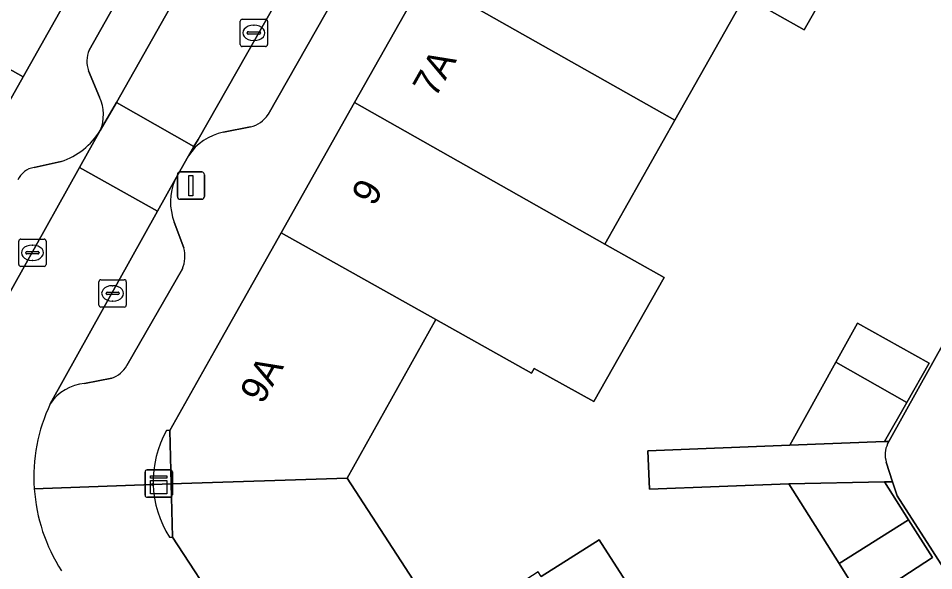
# Model space of a CAD drawing. Extents: x 161798 to 162385, y 382315 to 382833.
# Drawn here: x 162005.25 to 162038.73, y 382639.59 to 382659.78 of the extents above; entities that cross this region are included whole.
import ezdxf

# ---------------------------------------------------------------- set-up
doc = ezdxf.new("R2010")
doc.units = 0
for name, color, linetype in [('IMGEO_Erf', 7, 'Continuous'), ('IMGEO_Kast', 7, 'Continuous'), ('IMGEO_Kolk', 7, 'Continuous'), ('IMGEO_Lichtmast', 7, 'Continuous'), ('IMGEO_Pand', 7, 'Continuous'), ('IMGEO_Pand_nummerreeks', 7, 'Continuous'), ('IMGEO_Pand_overbouw', 7, 'Continuous'), ('IMGEO_Parkeervlak_open', 7, 'Continuous'), ('IMGEO_Rijbaan_lokaal_open', 7, 'Continuous'), ('IMGEO_Voetpad_open', 7, 'Continuous')]:
    doc.layers.add(name, color=color, linetype=linetype)

msp = doc.modelspace()

# ---------------------------------------------------------------- linework, layer by layer
at = {"layer": 'IMGEO_Erf'}
for points in [[(162049.126, 382624.056), (162037.386, 382642.326), (162037.221, 382642.838), (162036.93, 382642.832), (162037.804, 382641.448), (162038.678, 382640.064), (162036.156, 382638.417), (162035.263, 382639.842), (162033.431, 382642.763), (162028.329, 382642.567), (162028.275, 382643.971), (162033.468, 382644.171), (162035.151, 382647.209), (162035.941, 382648.633), (162038.557, 382647.172), (162037.743, 382645.738), (162036.929, 382644.304), (162037.089, 382644.31), (162054.299, 382675.209)], [(162036.559, 382663.871), (162033.985, 382659.354), (162031.821, 382660.586), (162029.259, 382656.056), (162026.698, 382651.527), (162028.865, 382650.298), (162026.302, 382645.768), (162024.119, 382646.981), (162024.02, 382646.802), (162020.518, 382648.763), (162017.274, 382642.968), (162020.91, 382637.369)], [(162024.369, 382639.367), (162026.492, 382640.715), (162029.297, 382636.356)]]:
    msp.add_lwpolyline(points, dxfattribs=at)
at = {"layer": 'IMGEO_Kast'}
for p, q in [((162009.961, 382643.268), (162010.802, 382643.268)), ((162010.802, 382643.268), (162009.961, 382643.268)), ((162009.886, 382642.343), (162009.886, 382643.184)), ((162009.886, 382643.184), (162009.886, 382642.343)), ((162010.886, 382643.193), (162010.886, 382642.352)), ((162010.886, 382642.352), (162010.886, 382643.193)), ((162010.811, 382642.268), (162009.97, 382642.268)), ((162009.97, 382642.268), (162010.811, 382642.268))]:
    msp.add_line(p, q, dxfattribs=at)
for points in [[(162010.081, 382643.058), (162010.681, 382643.058), (162010.681, 382642.973), (162010.081, 382642.973), (162010.081, 382643.058)], [(162010.081, 382642.883), (162010.681, 382642.883), (162010.681, 382642.394), (162010.081, 382642.394), (162010.081, 382642.883)]]:
    msp.add_lwpolyline(points, dxfattribs=at)
msp.add_circle((162010.165, 382642.732), 0.0377, dxfattribs=at)
for centre, start, end in [((162009.964, 382643.19), 92.4484, 184.2845), ((162009.964, 382643.19), 92.4484, 184.2845), ((162010.808, 382643.19), 2.4484, 94.2845), ((162010.808, 382643.19), 2.4484, 94.2845), ((162009.964, 382642.346), 182.4484, 274.2845), ((162009.964, 382642.346), 182.4484, 274.2845), ((162010.808, 382642.346), 272.4484, 4.2845), ((162010.808, 382642.346), 272.4484, 4.2845)]:
    msp.add_arc(centre, 0.0779, start, end, dxfattribs=at)
at = {"layer": 'IMGEO_Kolk'}
for p, q in [((162013.363, 382658.819), (162013.363, 382659.671)), ((162013.438, 382659.745), (162014.29, 382659.745)), ((162014.364, 382659.671), (162014.364, 382658.819)), ((162013.665, 382659.288), (162014.063, 382659.288)), ((162013.851, 382659.525), (162013.876, 382659.525)), ((162013.622, 382659.239), (162013.622, 382659.251)), ((162014.06, 382659.202), (162013.662, 382659.202)), ((162013.874, 382658.965), (162013.849, 382658.965)), ((162014.106, 382659.251), (162014.106, 382659.239)), ((162014.29, 382658.745), (162013.438, 382658.745)), ((162005.267, 382650.781), (162005.267, 382651.633)), ((162005.342, 382651.707), (162006.194, 382651.707)), ((162006.268, 382651.633), (162006.268, 382650.781)), ((162005.569, 382651.25), (162005.967, 382651.25)), ((162005.755, 382651.487), (162005.78, 382651.487)), ((162005.526, 382651.201), (162005.526, 382651.213)), ((162005.964, 382651.164), (162005.566, 382651.164)), ((162005.778, 382650.927), (162005.753, 382650.927)), ((162006.01, 382651.213), (162006.01, 382651.201)), ((162006.194, 382650.707), (162005.342, 382650.707)), ((162008.199, 382649.297), (162008.199, 382650.149)), ((162008.274, 382650.223), (162009.126, 382650.223)), ((162008.687, 382650.003), (162008.712, 382650.003)), ((162009.2, 382650.149), (162009.2, 382649.297)), ((162008.458, 382649.717), (162008.458, 382649.729)), ((162008.896, 382649.68), (162008.498, 382649.68)), ((162008.501, 382649.766), (162008.899, 382649.766)), ((162008.942, 382649.729), (162008.942, 382649.717)), ((162008.71, 382649.443), (162008.685, 382649.443)), ((162009.126, 382649.223), (162008.274, 382649.223))]:
    msp.add_line(p, q, dxfattribs=at)
for points in [[(162013.363, 382658.819), (162013.363, 382659.671)], [(162013.438, 382659.745), (162014.29, 382659.745)], [(162014.364, 382659.671), (162014.364, 382658.819)], [(162014.29, 382658.745), (162013.438, 382658.745)], [(162005.267, 382650.781), (162005.267, 382651.633)], [(162005.342, 382651.707), (162006.194, 382651.707)], [(162006.268, 382651.633), (162006.268, 382650.781)], [(162006.194, 382650.707), (162005.342, 382650.707)], [(162008.199, 382649.297), (162008.199, 382650.149)], [(162008.274, 382650.223), (162009.126, 382650.223)], [(162009.2, 382650.149), (162009.2, 382649.297)], [(162009.126, 382649.223), (162008.274, 382649.223)]]:
    msp.add_lwpolyline(points, dxfattribs=at)
for centre, radius, start, end in [((162013.44, 382659.669), 0.0765, 91.552, 178.448), ((162013.44, 382659.669), 0.0765, 91.552, 178.448), ((162014.288, 382659.669), 0.0765, 1.552, 88.448), ((162014.288, 382659.669), 0.0765, 1.552, 88.448), ((162013.662, 382659.248), 0.0403, 85.8775, 175.7526), ((162014.067, 382659.25), 0.0386, 1.7309, 96.639), ((162013.659, 382659.238), 0.0366, 178.938, 274.7102), ((162014.063, 382659.245), 0.043, 264.8664, 352.4533), ((162013.44, 382658.821), 0.0765, 181.552, 268.448), ((162013.44, 382658.821), 0.0765, 181.552, 268.448), ((162014.288, 382658.821), 0.0765, 271.552, 358.448), ((162014.288, 382658.821), 0.0765, 271.552, 358.448), ((162005.344, 382651.631), 0.0765, 91.552, 178.448), ((162005.344, 382651.631), 0.0765, 91.552, 178.448), ((162006.192, 382651.631), 0.0765, 1.552, 88.448), ((162006.192, 382651.631), 0.0765, 1.552, 88.448), ((162005.566, 382651.21), 0.0403, 85.8775, 175.7526), ((162005.971, 382651.212), 0.0386, 1.7309, 96.639), ((162005.563, 382651.2), 0.0366, 178.938, 274.7102), ((162005.967, 382651.207), 0.043, 264.8664, 352.4533), ((162005.344, 382650.783), 0.0765, 181.552, 268.448), ((162005.344, 382650.783), 0.0765, 181.552, 268.448), ((162006.192, 382650.783), 0.0765, 271.552, 358.448), ((162006.192, 382650.783), 0.0765, 271.552, 358.448), ((162008.276, 382650.147), 0.0765, 91.552, 178.448), ((162008.276, 382650.147), 0.0765, 91.552, 178.448), ((162009.124, 382650.147), 0.0765, 1.552, 88.448), ((162009.124, 382650.147), 0.0765, 1.552, 88.448), ((162008.498, 382649.726), 0.0403, 85.8775, 175.7526), ((162008.495, 382649.716), 0.0366, 178.938, 274.7102), ((162008.899, 382649.723), 0.043, 264.8664, 352.4533), ((162008.903, 382649.728), 0.0386, 1.7309, 96.639), ((162008.276, 382649.299), 0.0765, 181.552, 268.448), ((162008.276, 382649.299), 0.0765, 181.552, 268.448), ((162009.124, 382649.299), 0.0765, 271.552, 358.448), ((162009.124, 382649.299), 0.0765, 271.552, 358.448)]:
    msp.add_arc(centre, radius, start, end, dxfattribs=at)
for centre, major_axis, ratio, start_param, end_param in [((162013.85, 382659.245), (-0.387, 0.002), 0.722429, 4.712389, 7.853982), ((162013.875, 382659.245), (-0.39, 0.002), 0.717154, 1.570796, 4.712389), ((162005.754, 382651.207), (-0.387, 0.002), 0.722429, 4.712389, 7.853982), ((162005.779, 382651.207), (-0.39, 0.002), 0.717154, 1.570796, 4.712389), ((162008.686, 382649.723), (-0.387, 0.002), 0.722429, 4.712389, 7.853982), ((162008.711, 382649.723), (-0.39, 0.002), 0.717154, 1.570796, 4.712389)]:
    msp.add_ellipse(centre, major_axis=major_axis, ratio=ratio, start_param=start_param, end_param=end_param, dxfattribs=at)
at = {"layer": 'IMGEO_Lichtmast'}
for p, q in [((162011.067, 382653.262), (162011.067, 382654.062)), ((162011.067, 382654.062), (162011.067, 382653.262)), ((162011.167, 382654.162), (162011.957, 382654.162)), ((162011.957, 382654.162), (162011.167, 382654.162)), ((162012.057, 382654.062), (162012.057, 382653.262)), ((162012.057, 382653.262), (162012.057, 382654.062)), ((162011.957, 382653.162), (162011.167, 382653.162)), ((162011.167, 382653.162), (162011.957, 382653.162))]:
    msp.add_line(p, q, dxfattribs=at)
msp.add_lwpolyline([(162011.487, 382654.037), (162011.637, 382654.037), (162011.637, 382653.287), (162011.487, 382653.287), (162011.487, 382654.037)], dxfattribs=at)
for centre, start, end in [((162011.167, 382654.062), 90, 180), ((162011.167, 382654.062), 90, 180), ((162011.957, 382654.062), 0, 90), ((162011.957, 382654.062), 360, 90), ((162011.167, 382653.262), 180, 270), ((162011.167, 382653.262), 180, 270), ((162011.957, 382653.262), 270, 0), ((162011.957, 382653.262), 270, 0)]:
    msp.add_arc(centre, 0.1, start, end, dxfattribs=at)
at = {"layer": 'IMGEO_Pand'}
for points in [[(162025.211, 382670.282), (162022.663, 382665.766), (162031.821, 382660.586), (162033.985, 382659.354), (162036.559, 382663.871), (162034.369, 382665.109)], [(161995.988, 382662.954), (162005.425, 382657.64), (162009.351, 382664.611), (161999.855, 382669.821), (161998.116, 382666.733), (161995.726, 382668.073), (161994.033, 382665.067), (161996.423, 382663.727)], [(162022.663, 382665.766), (162020.106, 382661.234), (162029.259, 382656.056), (162031.821, 382660.586)], [(161995.988, 382662.954), (161994.681, 382660.634), (161996.969, 382659.351), (161996.165, 382657.924), (161995.358, 382658.378), (161994.707, 382657.222), (162002.666, 382652.742), (162005.425, 382657.64)], [(162020.106, 382661.234), (162017.55, 382656.702), (162026.698, 382651.527), (162029.259, 382656.056)], [(162017.55, 382656.702), (162014.858, 382651.931), (162020.518, 382648.763), (162024.02, 382646.802), (162024.119, 382646.981), (162026.302, 382645.768), (162028.865, 382650.298), (162026.698, 382651.527)], [(162020.518, 382648.763), (162014.858, 382651.931), (162012.434, 382647.634), (162010.786, 382644.712), (162010.84, 382642.761), (162017.274, 382642.968)], [(162035.151, 382647.209), (162037.743, 382645.738), (162038.557, 382647.172), (162035.941, 382648.633)], [(162037.743, 382645.738), (162035.151, 382647.209), (162033.468, 382644.171), (162036.929, 382644.304)], [(162017.274, 382642.968), (162010.84, 382642.761), (162010.894, 382640.81), (162012.701, 382638.028), (162015.436, 382633.815), (162020.91, 382637.369)], [(162035.263, 382639.842), (162037.804, 382641.448), (162036.93, 382642.832), (162033.431, 382642.763)], [(162037.804, 382641.448), (162035.263, 382639.842), (162036.156, 382638.417), (162038.678, 382640.064)], [(162027.216, 382634.987), (162029.297, 382636.356), (162026.492, 382640.715), (162024.369, 382639.367), (162024.258, 382639.542), (162020.91, 382637.369), (162015.436, 382633.815), (162018.386, 382629.27)]]:
    msp.add_lwpolyline(points, close=True, dxfattribs=at)
at = {"layer": 'IMGEO_Pand_overbouw'}
for points in [[(162010.786, 382644.712), (162010.671, 382644.709), (162010.553, 382644.481), (162010.45, 382644.247), (162010.364, 382644.005), (162010.294, 382643.759), (162010.241, 382643.508), (162010.205, 382643.255), (162010.186, 382642.999), (162010.184, 382642.74), (162010.84, 382642.761)], [(162010.84, 382642.761), (162010.184, 382642.74), (162010.2, 382642.487), (162010.233, 382642.233), (162010.283, 382641.982), (162010.35, 382641.734), (162010.433, 382641.492), (162010.533, 382641.256), (162010.648, 382641.027), (162010.779, 382640.807), (162010.894, 382640.81)]]:
    msp.add_lwpolyline(points, close=True, dxfattribs=at)
at = {"layer": 'IMGEO_Parkeervlak_open'}
for points in [[(162008.246, 382655.671), (162008.841, 382656.703), (162030.647, 382695.267)], [(162018.224, 382677.013), (162016.625, 382674.182), (162014.387, 382670.217), (162007.838, 382658.619)], [(162021.396, 382672.067), (162018.058, 382666.344), (162015.013, 382660.948), (162011.822, 382655.343), (162011.674, 382655.092), (162011.474, 382654.753)], [(162014.383, 382656.258), (162016.505, 382659.985), (162019.617, 382665.474), (162021.642, 382668.994)], [(162007.814, 382657.858), (162008.224, 382656.893)], [(162007.492, 382654.325), (162008.246, 382655.671)], [(162012.75, 382655.616), (162013.742, 382655.816)], [(162003.451, 382647.107), (162007.492, 382654.325)], [(162006.819, 382654.54), (162005.831, 382654.321)], [(162010.991, 382653.885), (162010.343, 382652.722), (162006.42, 382645.688)], [(162011.305, 382651.389), (162010.956, 382652.322)], [(162009.224, 382647.081), (162011.249, 382650.618)], [(162007.67, 382646.43), (162008.667, 382646.621)]]:
    msp.add_lwpolyline(points, dxfattribs=at)
for centre, radius, start, end in [((162008.89, 382658.205), 1.13, 158.509, 197.8783), ((162006.841, 382656.257), 1.523, 337.3685, 24.6943), ((162013.536, 382656.8), 1.006, 281.8095, 327.3667), ((162005.922, 382657.138), 2.749, 289.0559, 327.7428), ((162013.144, 382653.659), 1.996, 101.3748, 146.7687), ((162005.937, 382653.563), 0.766, 97.9315, 156.5722), ((162012.84, 382653.062), 2.024, 155.9944, 201.44), ((162010.184, 382651.083), 1.162, 336.4214, 15.27), ((162008.281, 382647.655), 1.104, 290.4555, 328.6479), ((162007.832, 382644.733), 1.704, 95.4497, 145.9371)]:
    msp.add_arc(centre, radius, start, end, dxfattribs=at)
at = {"layer": 'IMGEO_Rijbaan_lokaal_open'}
for points in [[(162030.256, 382687.882), (162031.162, 382689.492), (162033.045, 382692.848), (162033.513, 382693.664), (162030.647, 382695.267), (162008.841, 382656.703), (162011.674, 382655.092), (162011.822, 382655.343), (162015.013, 382660.948), (162018.058, 382666.344), (162021.396, 382672.067), (162021.983, 382673.097)], [(162011.474, 382654.753), (162011.674, 382655.092), (162008.841, 382656.703), (162008.246, 382655.671), (162007.492, 382654.325), (162010.343, 382652.722), (162010.991, 382653.885)]]:
    msp.add_lwpolyline(points, close=True, dxfattribs=at)
for points in [[(162094.025, 382644.065), (162096.732, 382648.306), (162088.266, 382653.675), (162087.562, 382654.137), (162076.445, 382661.19), (162075.75, 382661.625), (162065.37, 382668.189), (162064.691, 382668.651), (162054.299, 382675.209), (162037.089, 382644.31), (162037.04, 382644.222)], [(162006.42, 382645.688), (162010.343, 382652.722), (162007.492, 382654.325), (162003.451, 382647.107), (162001.269, 382643.469), (162001.034, 382642.937)], [(162036.992, 382643.55), (162037.221, 382642.838), (162037.386, 382642.326), (162049.126, 382624.056), (162049.733, 382623.111)]]:
    msp.add_lwpolyline(points, dxfattribs=at)
for centre, radius, start, end in [((162012.114, 382643.006), 6.294, 154.7746, 183.8502), ((162037.852, 382643.826), 0.903, 154.0085, 197.8203), ((162012.101, 382643.002), 6.281, 183.8273, 212.9623)]:
    msp.add_arc(centre, radius, start, end, dxfattribs=at)
at = {"layer": 'IMGEO_Voetpad_open'}
for points in [[(162045.819, 382722.219), (162043.809, 382725.145), (162038.323, 382719.109), (162039.623, 382717.887), (162032.096, 382704.768), (162030.046, 382701.359), (162026.271, 382694.655), (162022.485, 382687.932), (162019.684, 382682.959), (162015.615, 382675.734), (162015.046, 382674.723), (162012.489, 382670.184), (162009.351, 382664.611), (162005.425, 382657.64), (162002.666, 382652.742), (162000, 382648.009), (161998.381, 382645.135), (161995.375, 382646.828), (161994.867, 382646.022), (161990.55, 382641.902), (161994.605, 382633.896), (161994.989, 382632.3)], [(162005.834, 382642.583), (162010.84, 382642.761), (162010.786, 382644.712), (162012.434, 382647.634), (162014.858, 382651.931), (162017.55, 382656.702), (162020.106, 382661.234), (162022.663, 382665.766), (162025.211, 382670.282), (162027.764, 382674.809), (162030.318, 382679.335), (162032.949, 382683.998), (162035.537, 382688.587), (162034.816, 382688.989), (162036.014, 382691.139), (162035.919, 382691.194), (162038.529, 382695.832)], [(162007.838, 382658.619), (162014.387, 382670.217), (162013.964, 382670.454), (162016.194, 382674.424), (162016.625, 382674.182), (162018.224, 382677.013)], [(162021.642, 382668.994), (162019.617, 382665.474), (162016.505, 382659.985), (162014.383, 382656.258)], [(162008.224, 382656.893), (162007.814, 382657.858)], [(162013.742, 382655.816), (162012.75, 382655.616)], [(162011.474, 382654.753), (162010.991, 382653.885)], [(162005.831, 382654.321), (162006.819, 382654.54)], [(162010.956, 382652.322), (162011.305, 382651.389)], [(162011.249, 382650.618), (162009.224, 382647.081)], [(162008.667, 382646.621), (162007.67, 382646.43)], [(162037.04, 382644.222), (162037.089, 382644.31), (162036.929, 382644.304), (162033.468, 382644.171), (162028.275, 382643.971), (162028.329, 382642.567), (162033.431, 382642.763), (162036.93, 382642.832), (162037.221, 382642.838), (162036.992, 382643.55)], [(162030.21, 382608.441), (162030.121, 382608.598), (162029.039, 382610.271), (162038.237, 382616.236), (162037.876, 382616.839), (162029.843, 382611.625), (162026.866, 382616.209), (162024.025, 382620.584), (162021.208, 382624.924), (162018.386, 382629.27), (162015.436, 382633.815), (162012.701, 382638.028), (162010.894, 382640.81), (162010.84, 382642.761), (162005.834, 382642.583)]]:
    msp.add_lwpolyline(points, dxfattribs=at)
for centre, radius, start, end in [((162008.89, 382658.205), 1.13, 158.509, 197.8783), ((162006.841, 382656.257), 1.523, 337.3685, 24.6943), ((162013.536, 382656.8), 1.006, 281.8095, 327.3667), ((162005.922, 382657.138), 2.749, 289.0559, 327.7428), ((162013.144, 382653.659), 1.996, 101.3748, 146.7687), ((162005.937, 382653.563), 0.766, 97.9315, 156.5722), ((162012.84, 382653.062), 2.024, 155.9944, 201.44), ((162010.184, 382651.083), 1.162, 336.4214, 15.27), ((162008.281, 382647.655), 1.104, 290.4555, 328.6479), ((162007.832, 382644.733), 1.704, 95.4497, 145.9371), ((162012.114, 382643.006), 6.294, 154.7746, 183.8502), ((162037.852, 382643.826), 0.903, 154.0085, 197.8203), ((162012.101, 382643.002), 6.281, 183.8273, 212.9623)]:
    msp.add_arc(centre, radius, start, end, dxfattribs=at)

# ---------------------------------------------------------------- texts
at = {"layer": 'IMGEO_Pand_nummerreeks'}
for s, p in [('7A', (162020.495, 382656.835)), ('9', (162018.257, 382652.867)), ('9A', (162014.176, 382645.633))]:
    msp.add_text(s, height=1, rotation=60.5713, dxfattribs=at).set_placement(p)

doc.saveas('drawing.dxf')
